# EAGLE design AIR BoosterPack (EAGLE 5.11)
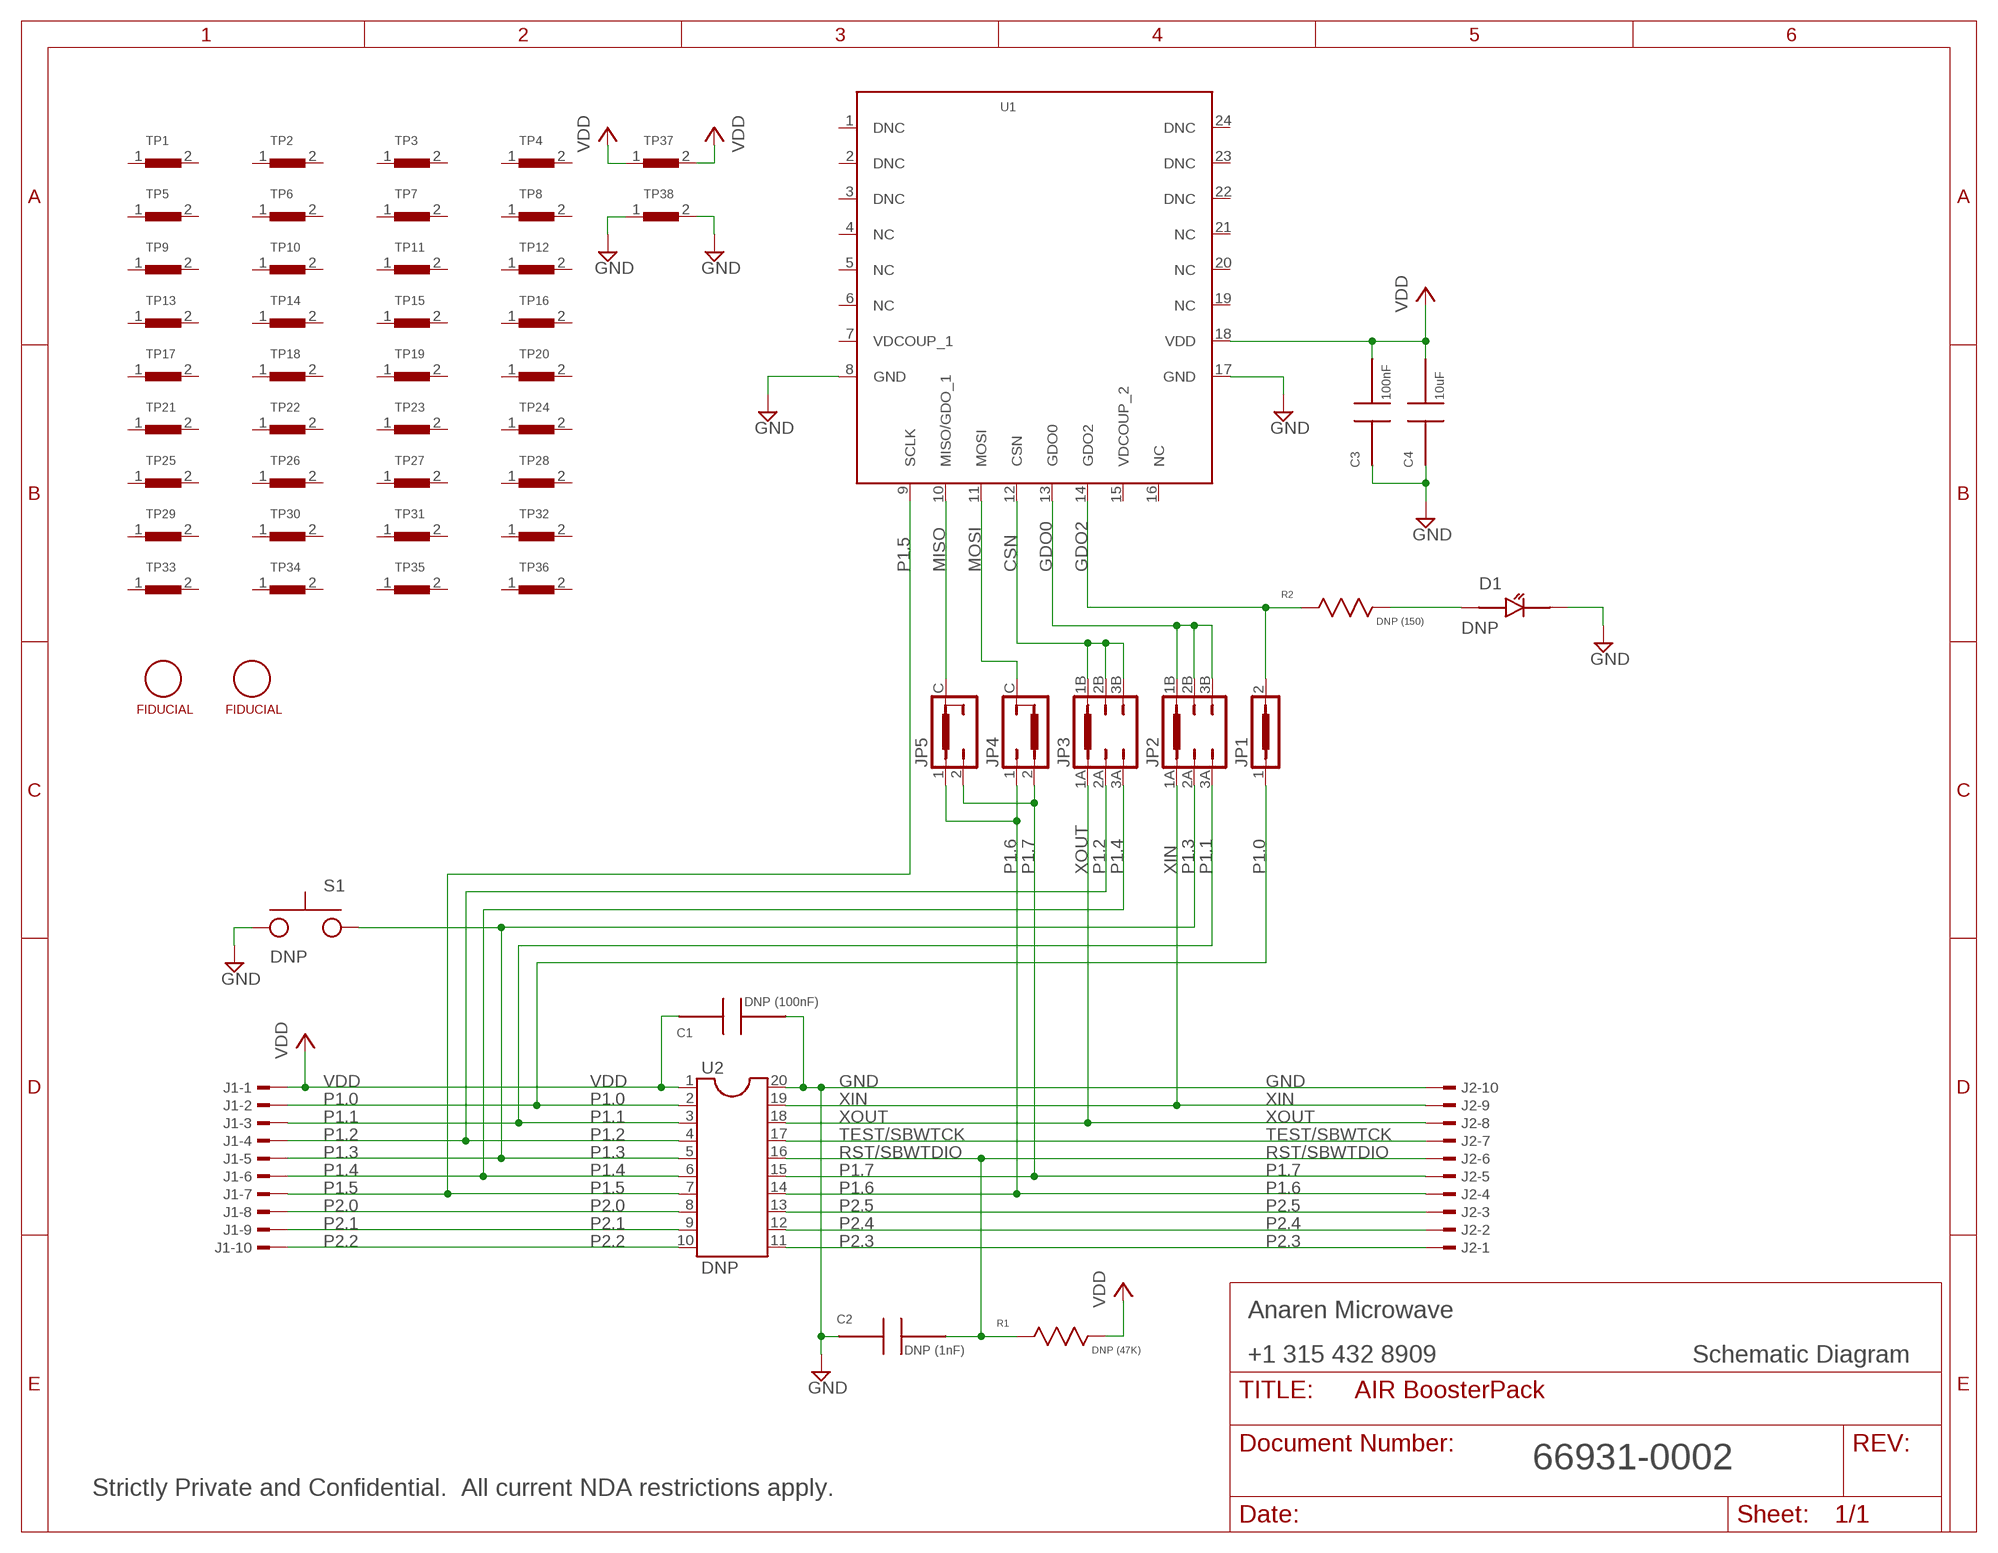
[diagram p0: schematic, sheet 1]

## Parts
C1  DNP (100nF)  C0603  [CAPC1608X90N]
C2  DNP (1nF)  C0603  [CAPC1608X90N]
C3  100nF  C0603  [CAPC1608X90N]
C4  10uF  C0603  [CAPC1608X90N]
D1  DNP  LED_SMT_0603  [LEDC1608X80N]
J1  TSW-110-02-S-S  [TSW-110-02-S-S]
J2  TSW-110-02-S-S  [TSW-110-02-S-S]
JP1  JP0603_1P_A  [JP0603_1P_A]
JP2  JP0603_3P_A  [JP0603_3P_A]
JP3  JP0603_3P_A  [JP0603_3P_A]
JP4  JP0603_2C_B  [JP0603_2C_B]
JP5  JP0603_2C_A  [JP0603_2C_A]
R1  DNP (47K)  R0603  [RESC1608X50AN]
R2  DNP (150)  R0603  [RESC1608X50AN]
S1  DNP  SWITCH_B3U-1000P  [SWITCH_B3U-1000P]
TP1  PROTO_100MIL_2P  [PROTO_100MIL_2P]
TP2  PROTO_100MIL_2P  [PROTO_100MIL_2P]
TP3  PROTO_100MIL_2P  [PROTO_100MIL_2P]
TP4  PROTO_100MIL_2P  [PROTO_100MIL_2P]
TP5  PROTO_100MIL_2P  [PROTO_100MIL_2P]
TP6  PROTO_100MIL_2P  [PROTO_100MIL_2P]
TP7  PROTO_100MIL_2P  [PROTO_100MIL_2P]
TP8  PROTO_100MIL_2P  [PROTO_100MIL_2P]
TP9  PROTO_100MIL_2P  [PROTO_100MIL_2P]
TP10  PROTO_100MIL_2P  [PROTO_100MIL_2P]
TP11  PROTO_100MIL_2P  [PROTO_100MIL_2P]
TP12  PROTO_100MIL_2P  [PROTO_100MIL_2P]
TP13  PROTO_100MIL_2P  [PROTO_100MIL_2P]
TP14  PROTO_100MIL_2P  [PROTO_100MIL_2P]
TP15  PROTO_100MIL_2P  [PROTO_100MIL_2P]
TP16  PROTO_100MIL_2P  [PROTO_100MIL_2P]
TP17  PROTO_100MIL_2P  [PROTO_100MIL_2P]
TP18  PROTO_100MIL_2P  [PROTO_100MIL_2P]
TP19  PROTO_100MIL_2P  [PROTO_100MIL_2P]
TP20  PROTO_100MIL_2P  [PROTO_100MIL_2P]
TP21  PROTO_100MIL_2P  [PROTO_100MIL_2P]
TP22  PROTO_100MIL_2P  [PROTO_100MIL_2P]
TP23  PROTO_100MIL_2P  [PROTO_100MIL_2P]
TP24  PROTO_100MIL_2P  [PROTO_100MIL_2P]
TP25  PROTO_100MIL_2P  [PROTO_100MIL_2P]
TP26  PROTO_100MIL_2P  [PROTO_100MIL_2P]
TP27  PROTO_100MIL_2P  [PROTO_100MIL_2P]
TP28  PROTO_100MIL_2P  [PROTO_100MIL_2P]
TP29  PROTO_100MIL_2P  [PROTO_100MIL_2P]
TP30  PROTO_100MIL_2P  [PROTO_100MIL_2P]
TP31  PROTO_100MIL_2P  [PROTO_100MIL_2P]
TP32  PROTO_100MIL_2P  [PROTO_100MIL_2P]
TP33  PROTO_100MIL_2P  [PROTO_100MIL_2P]
TP34  PROTO_100MIL_2P  [PROTO_100MIL_2P]
TP35  PROTO_100MIL_2P  [PROTO_100MIL_2P]
TP36  PROTO_100MIL_2P  [PROTO_100MIL_2P]
TP37  PROTO_100MIL_2P  [PROTO_100MIL_2P]
TP38  PROTO_100MIL_2P  [PROTO_100MIL_2P]
U1  A1101R09A  [A1101R09A]
U2  DNP  DIL20  [DIL20]
U$3  FIDUCIAL  FIDUCIAL1.0MM  [FIDUCIAL_1.0MM]
U$4  FIDUCIAL  FIDUCIAL1.0MM  [FIDUCIAL_1.0MM]

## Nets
CSN: JP3.1B JP3.2B JP3.3B U1.12(CSN)
GDO0: JP2.1B JP2.2B JP2.3B U1.13(GDO0)
GDO2: JP1.2 R2.P$1(P1) U1.14(GDO2)
GND: C1.P$2 C2.P$1 C3.P$1 C4.P$1 D1.P$2 J2.10 S1.1 TP38.1 TP38.2 U1.8(GND) U1.17(GND) U2.20
MISO: JP5.C U1.10(MISO/GDO_1)
MOSI: JP4.C U1.11(MOSI)
N$3: D1.P$1 R2.P$2(P2)
P1.0: J1.2 JP1.1 U2.2
P1.1: J1.3 JP2.3A U2.3
P1.2: J1.4 JP3.2A U2.4
P1.3: J1.5 JP2.2A S1.2 U2.5
P1.4: J1.6 JP3.3A U2.6
P1.5: J1.7 U1.9(SCLK) U2.7
P1.6: J2.4 JP4.1 JP5.1 U2.14
P1.7: J2.5 JP4.2 JP5.2 U2.15
P2.0: J1.8 U2.8
P2.1: J1.9 U2.9
P2.2: J1.10 U2.10
P2.3: J2.1 U2.11
P2.4: J2.2 U2.12
P2.5: J2.3 U2.13
RST/SBWTDIO: C2.P$2 J2.6 R1.P$1(P1) U2.16
TEST/SBWTCK: J2.7 U2.17
VDD [PWR]: C1.P$1 C3.P$2 C4.P$2 J1.1 R1.P$2(P2) TP37.1 TP37.2 U1.18(VDD) U2.1
XIN: J2.9 JP2.1A U2.19
XOUT: J2.8 JP3.1A U2.18
Unconnected: TP1.1 TP1.2 TP2.1 TP2.2 TP3.1 TP3.2 TP4.1 TP4.2 TP5.1 TP5.2 TP6.1 TP6.2 TP7.1 TP7.2 TP8.1 TP8.2 TP9.1 TP9.2 TP10.1 TP10.2 TP11.1 TP11.2 TP12.1 TP12.2 TP13.1 TP13.2 TP14.1 TP14.2 TP15.1 TP15.2 TP16.1 TP16.2 TP17.1 TP17.2 TP18.1 TP18.2 TP19.1 TP19.2 TP20.1 TP20.2 TP21.1 TP21.2 TP22.1 TP22.2 TP23.1 TP23.2 TP24.1 TP24.2 TP25.1 TP25.2 TP26.1 TP26.2 TP27.1 TP27.2 TP28.1 TP28.2 TP29.1 TP29.2 TP30.1 TP30.2 TP31.1 TP31.2 TP32.1 TP32.2 TP33.1 TP33.2 TP34.1 TP34.2 TP35.1 TP35.2 TP36.1 TP36.2 U1.1(DNC) U1.2(DNC) U1.3(DNC) U1.4(NC) U1.5(NC) U1.6(NC) U1.7(VDCOUP_1) U1.15(VDCOUP_2) U1.16(NC) U1.19(NC) U1.20(NC) U1.21(NC) U1.22(DNC) U1.23(DNC) U1.24(DNC)

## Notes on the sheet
- Anaren Microwave
- +1 315 432 8909 | Schematic Diagram
- 66931-0002
- Strictly Private and Confidential.  All current NDA restrictions apply.

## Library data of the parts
C1-C4 = Anaren_MGS:C0603
D1 = Anaren_MGS:LED_SMT_0603
J1 J2 = con-samtec:TSW-110-02-S-S: THROUGH-HOLE .025" SQ POST HEADER Source: Samtec TSW.pdf; OC_FARNELL: unknown; OC_NEWARK: unknown
JP1 = Anaren_MGS:JP0603_1P_A
JP2 JP3 = Anaren_MGS:JP0603_3P_A: JUMPER
JP4 = Anaren_MGS:JP0603_2C_B
JP5 = Anaren_MGS:JP0603_2C_A
R1 R2 = Anaren_MGS:R0603
S1 = Anaren_MGS:SWITCH_B3U-1000P: 1.2 X 3.0mm TACT Switch (SMD)
TP1-TP38 = Anaren_MGS:PROTO_100MIL_2P
U1 = Anaren_1:A1101R09*
U2 = ic-package:DIL20: Dual In Line / Socket
U$3 U$4 = Anaren_1:FIDUCIAL

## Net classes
0 default: clearance 0.254 mm
1 PWR: clearance 0.381 mm

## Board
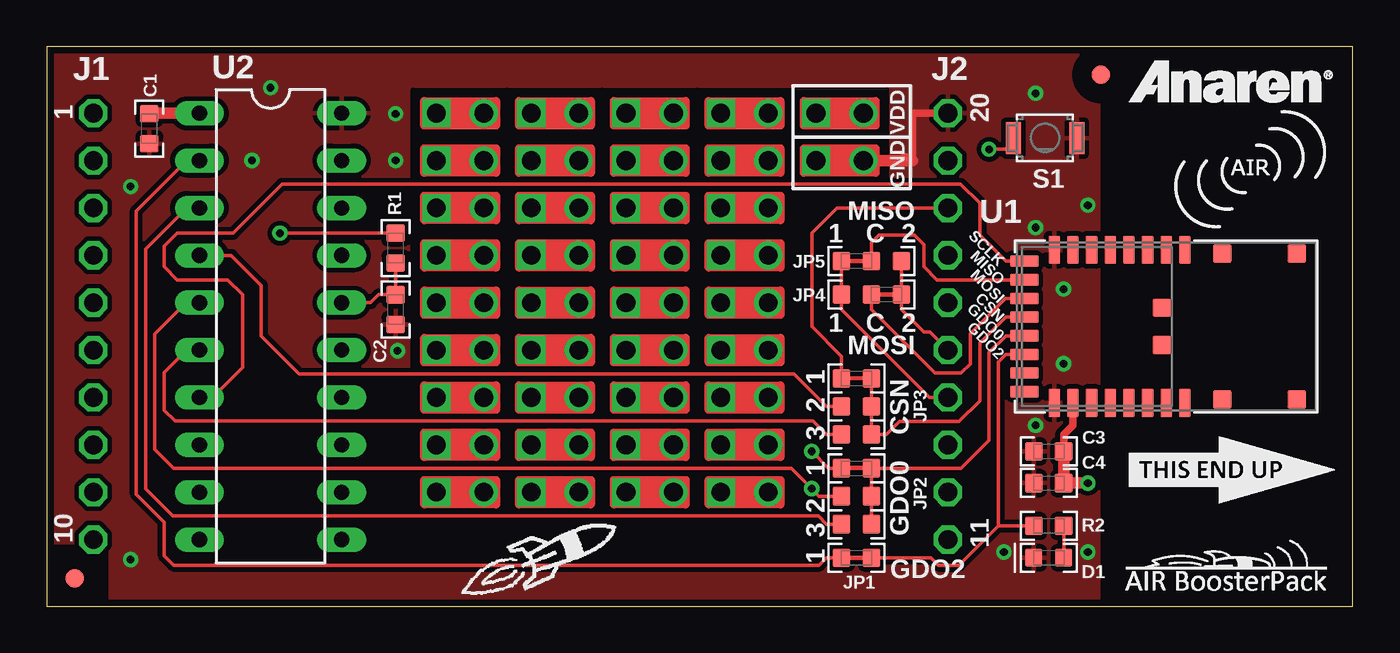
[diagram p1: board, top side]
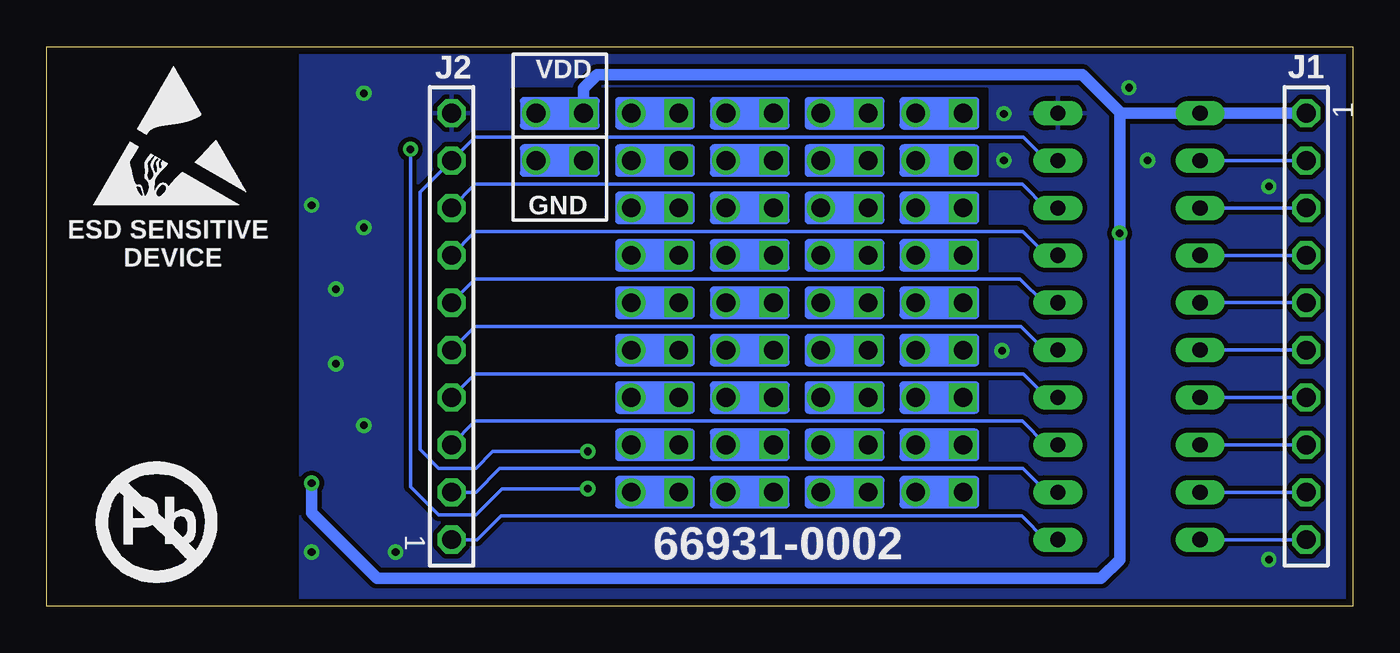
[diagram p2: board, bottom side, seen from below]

Size 70 x 30 mm. Coordinates in mm from the lower left corner, seen from the top.
Outline: 0,0 70,0 70,30 0,30 0,0
Copper layers (1*16): Top 0.035mm / dielectric 1.5mm / Bottom 0.035mm
Design rules "default *": minimum track width 0.2mm, minimum drill 16mil, track to track 8mil, track to pad 8mil, pad to pad 8mil, via to via 8mil, smd to smd 8mil, copper to edge 15mil, drill to drill 8mil, minimum pad ring 10mil, minimum via ring 8mil, stop-mask expansion 4mil, vias tented up to drill 0mil, thermal gap 10mil
tRestrict: area 0,0 to 3.3,3.3; area 55.5,28.5 to 58.5,30

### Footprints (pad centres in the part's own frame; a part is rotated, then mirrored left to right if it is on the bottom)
CAPC1608X90N = smd 0.95 x 1: P$1 -0.8,0; P$2 0.8,0
LEDC1608X80N = smd 0.9 x 0.95: P$1 -0.8,0; P$2 0.8,0
TSW-110-02-S-S = drill 1 pad 1.5 octagon: 1 11.43,0; 2 8.89,0; 3 6.35,0; 4 3.81,0; 5 1.27,0; 6 -1.27,0; 7 -3.81,0; 8 -6.35,0; 9 -8.89,0; 10 -11.43,0
JP0603_1P_A = smd 0.95 x 1: 1 -0.8,0; 2 0.8,0
JP0603_3P_A = smd 0.95 x 1: 1A -0.8,1.5; 1B 0.8,1.5; 2A -0.8,0; 2B 0.8,0; 3A -0.8,-1.5; 3B 0.8,-1.5
JP0603_2C_B = smd 0.95 x 1: 1 -1.6,0; 2 1.6,0; C 0,0
JP0603_2C_A = smd 0.95 x 1: 1 -1.6,0; 2 1.6,0; C 0,0
RESC1608X50AN = smd 0.95 x 1: P$1 -0.8,0; P$2 0.8,0
SWITCH_B3U-1000P = smd 0.8 x 1.7: 1 -1.7,0; 2 1.7,0
PROTO_100MIL_2P = drill 1 square: 1 -1.27,0 | drill 1 round: 2 1.27,0
A1101R09A = smd 1.5 x 0.61: 1 -4.105,4.5; 2 -4.105,3.5; 3 -4.105,2.5; 4 -4.105,1.5; 5 -4.105,0.5; 6 -4.105,-0.5; 7 -4.105,-1.5; 8 -4.105,-2.5; 17 4.105,-2.5; 18 4.105,-1.5; 19 4.105,-0.5; 20 4.105,0.5; 21 4.105,1.5; 22 4.105,2.5; 23 4.105,3.5; 24 4.105,4.5 | smd 0.61 x 1.5: 9 -3.5,-4.1; 10 -2.5,-4.1; 11 -1.5,-4.1; 12 -0.5,-4.1; 13 0.5,-4.1; 14 1.5,-4.1; 15 2.5,-4.1; 16 3.5,-4.1 | smd 1 x 1: P$25 -3.91,10.5; P$26 -3.91,6.5; P$27 -1,3.256; P$28 1,3.256; P$29 3.91,6.5; P$30 3.91,10.5
DIL20 = drill 0.813 long: 1 -11.43,-3.81; 2 -8.89,-3.81; 3 -6.35,-3.81; 4 -3.81,-3.81; 5 -1.27,-3.81; 6 1.27,-3.81; 7 3.81,-3.81; 8 6.35,-3.81; 9 8.89,-3.81; 10 11.43,-3.81; 11 11.43,3.81; 12 8.89,3.81; 13 6.35,3.81; 14 3.81,3.81; 15 1.27,3.81; 16 -1.27,3.81; 17 -3.81,3.81; 18 -6.35,3.81; 19 -8.89,3.81; 20 -11.43,3.81
FIDUCIAL_1.0MM = smd 1 x 1: P$1 0,0

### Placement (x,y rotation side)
C1  5.5,25.6 270 top
C2  18.7,15.9 90 top
C3  53.7,8.3 0 top
C4  53.7,6.6 0 top
D1  53.7,2.6 180 top
DRILEGEND  [DRILEGEND]  not placed on the board
J1  2.5,15 90 bottom
J2  48.3,15 270 bottom
JP1  43.4,2.6 0 top
JP2  43.4,5.9 0 top
JP3  43.4,10.7 0 top
JP4  44.2,16.7 0 top
JP5  44.2,18.5 0 top
R1  18.7,19.2 90 top
R2  53.7,4.3 0 top
S1  53.5,25.1 180 top
TP1  22.16,26.43 0 top
TP2  27.24,26.43 0 top
TP3  32.32,26.43 0 top
TP4  37.4,26.43 0 top
TP5  22.16,23.89 0 top
TP6  27.24,23.89 0 top
TP7  32.32,23.89 0 top
TP8  37.4,23.89 0 top
TP9  22.16,21.35 0 top
TP10  27.24,21.35 0 top
TP11  32.32,21.35 0 top
TP12  37.4,21.35 0 top
TP13  22.16,18.81 0 top
TP14  27.24,18.81 0 top
TP15  32.32,18.81 0 top
TP16  37.4,18.81 0 top
TP17  22.16,16.27 0 top
TP18  27.24,16.27 0 top
TP19  32.32,16.27 0 top
TP20  37.4,16.27 0 top
TP21  22.16,13.73 0 top
TP22  27.24,13.73 0 top
TP23  32.32,13.73 0 top
TP24  37.4,13.73 0 top
TP25  22.16,11.19 0 top
TP26  27.24,11.19 0 top
TP27  32.32,11.19 0 top
TP28  37.4,11.19 0 top
TP29  22.16,8.65 0 top
TP30  27.24,8.65 0 top
TP31  32.32,8.65 0 top
TP32  37.4,8.65 0 top
TP33  22.16,6.11 0 top
TP34  27.24,6.11 0 top
TP35  32.32,6.11 0 top
TP36  37.4,6.11 0 top
TP37  42.5,26.43 0 top
TP38  42.5,23.89 0 top
U1  56.5,15 270 top
U2  12,15 270 top
U$1  [REG_ANAREN_LOGO_SCALE_0.2]  58,27 0 top
U$3  1.5,1.5 0 top
U$4  56.5,28.5 0 top
U$5  [ESD_LOGO_SCALE_0.2]  67.5,21.5 0 bottom
U$9  [PB-FREE_LOGO_SCALE_1.0]  64,4.5 0 bottom
U$10  [ORIENTATION_ARROW_SCALE_0.6]  58,5.5 0 top
U$11  [AIR_LOGO_SCALE_0.2]  64.5,23.5 0 top
U$12  [LAUNCHPAD_ROCKET_NORF_SCALE_1.0]  22,0.2 0 top
U$13  [LAUNCHPAD_HALF_ROCKET_SCALE_1.0]  57.5,0.5 0 top

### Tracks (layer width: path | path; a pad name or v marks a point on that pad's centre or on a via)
CSN
  Top 0.2: JP3.1B JP3.2B JP3.3B 45,9.2 45.7,9.9 48.9,9.9 50,11 50,14.1 51.4,15.5 U1.12
GDO0
  Top 0.2: JP2.3B JP2.2B JP2.1B 49,7.4 50.5,8.9 50.5,13.6 51.4,14.5 U1.13
GDO2
  Top 0.2: JP1.2 47.4,2.6 47.8,2.2 48.9,2.2 51,4.3 | U1.14 51.4,13.5 51,13.1 51,4.3 | 51,4.3 R2.P$1
GND  (via drill 0.41)
  Top 0.406: J2.10 46.4,26.43 46.4,23.9
  Top 0.61: 46,24 46,23.9 | TP38.2 46.4,23.9 | TP38.2 | TP38.2 TP38.1
  other vias: 53,9.7 53,20.3 53,27.5 4.5,22.5 4.5,2.5 18.8,13.7 51.3,2.9 54.5,17 54.5,13 12,27.8 18.7,23.9 18.7,26.4 11,23.9 55.8,2.9 55.8,21.5
  pour Bottom: 0,0 0,30 56.4,30 56.4,0
  pour Top: 0,0 0,30 56.4,30 56.4,0
MISO
  Top 0.2: JP5.C 44.2,19.5 44.6,19.9 46.5,19.9 47,19.4 47,18.2 47.7,17.5 U1.10
MOSI
  Top 0.2: JP4.C 44.2,15.9 47.6,12.5 49,12.5 49.5,13 49.5,14.62 51.38,16.5 U1.11
N$3
  Top 0.2: R2.P$2 D1.P$1
P1.0
  Top 0.2: JP1.1 41.8,2.6 41.4,2.2 6.8,2.2 6.3,2.7 6.3,4.5 4.8,6 4.8,21.19 7.5,23.89 U2.2
  Bottom 0.2: U2.2 J1.2
P1.1
  Top 0.2: U2.3 7.5,21.35 5.3,19.15 5.3,6.3 6.76,4.84 41.36,4.84 41.8,4.4 JP2.3A
  Bottom 0.2: J1.3 U2.3 6.45,21.35
P1.2
  Top 0.2: U2.4 9.9,18.8 11.5,17.2 11.5,14.5 13.54,12.46 40.04,12.46 41.8,10.7 JP3.2A
  Bottom 0.2: J1.4 U2.4
P1.3  (via drill 0.41)
  Top 0.2: U2.5 7.47,16.27 5.8,14.6 5.8,8.4 6.82,7.38 39.92,7.38 v41,6.3 41.4,5.9 JP2.2A | v50.5,24.5 51.8,24.5 S1.2
  Bottom 0.2: U2.5 J1.5 | v41,6.3 45.6,6.3 47,4.9 49,4.9 50.5,6.4 v50.5,24.5
P1.4
  Top 0.2: U2.6 7.5,13.73 6.3,12.53 6.3,10.5 6.88,9.92 41.08,9.92 41.8,9.2 JP3.3A
  Bottom 0.2: J1.6 U2.6
P1.5
  Top 0.2: U1.9 51.4,18.5 50,19.9 50,21.6 48.98,22.62 12.62,22.62 10,20 7,20 6.3,19.3 6.3,18.2 7,17.5 9.7,17.5 10.5,16.7 10.5,12.8 8.89,11.19 U2.7
  Bottom 0.2: J1.7 U2.7
P1.6
  Top 0.2: JP5.1 JP4.1 42.6,15.9 47.3,11.2 J2.4
  Bottom 0.2: U2.14 16.39,11.19 17.66,12.46 47.03,12.46 J2.4
P1.7
  Top 0.2: JP5.2 JP4.2 45.8,15.9 47,14.7 47.33,14.7 J2.5
  Bottom 0.2: U2.15 16.53,13.73 17.8,15 47.03,15 J2.5
P2.0
  Bottom 0.2: J1.8 U2.8
P2.1
  Bottom 0.2: J1.9 U2.9
P2.2
  Bottom 0.2: J1.10 U2.10
P2.3
  Bottom 0.2: U2.11 16.47,3.57 17.74,4.84 45.66,4.84 46.93,3.57 J2.1
P2.4
  Bottom 0.2: U2.12 16.41,6.11 17.68,7.38 45.72,7.38 46.99,6.11 J2.2
P2.5
  Bottom 0.2: U2.13 16.45,8.65 17.72,9.92 47.03,9.92 J2.3
RST/SBWTDIO
  Top 0.2: R1.P$1 C2.P$2 17.8,16.7 17.37,16.27 U2.16
  Bottom 0.2: U2.16 16.57,16.27 17.84,17.54 47.03,17.54 J2.6
TEST/SBWTCK
  Bottom 0.2: U2.17 16.41,18.81 17.68,20.08 47.03,20.08 J2.7
VDD  (via drill 0.41)
  Top 0.2: v12.5,20 R1.P$2
  Top 0.406: U1.18 55,9.7 54.5,9.2 C3.P$2
  Top 0.61: C3.P$2 C4.P$2 v55.8,6.6 | U2.1 5.5,26.43 C1.P$1
  Bottom 0.61: J1.1 U2.1 12.5,26.43 | 12.5,26.43 v12.5,20 12.5,2.5 13.5,1.5 52.3,1.5 55.8,5 v55.8,6.6 | 12.5,26.43 12.5,26.5 14.5,28.5 40.5,28.5 41.23,27.77 TP37.1 TP37.2
XIN  (via drill 0.41)
  Top 0.2: v41,8.3 41.9,7.4 JP2.1A
  Bottom 0.2: J2.9 | J2.9 50,22.19 50,8.4 49,7.4 47,7.4 46.1,8.3 v41,8.3 | U2.19 16.39,23.89 17.66,25.16 47.03,25.16 J2.9
XOUT
  Top 0.2: J2.8 42.35,21.35 41,20 41,15 42.6,13.4 JP3.1A
  Bottom 0.2: U2.18 16.45,21.35 17.72,22.62 47.03,22.62 J2.8

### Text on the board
tPlace: J1 | VDD | J2 | 20 | 1 | GND | MISO | 1 | C | 2 | SCLK | MISO | MOSI | CSN | 1 | C | 2 | GDO0 | MOSI | GDO2 | 1 | CSN | 2 | 3 | GDO0 | 1 | 2 | 11 | 3 | 10 | 1 | GDO2
bPlace: VDD | GND | ESD SENSITIVE | DEVICE | 66931-0002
